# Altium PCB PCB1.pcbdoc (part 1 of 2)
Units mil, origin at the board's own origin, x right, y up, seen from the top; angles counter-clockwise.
Board outline 2362.2 x 2361.9 mil, 2 copper layers (Top Layer, Bottom Layer), stack 62.2 mil thick; 39 components, 38 nets, 262 pads, 86 vias.
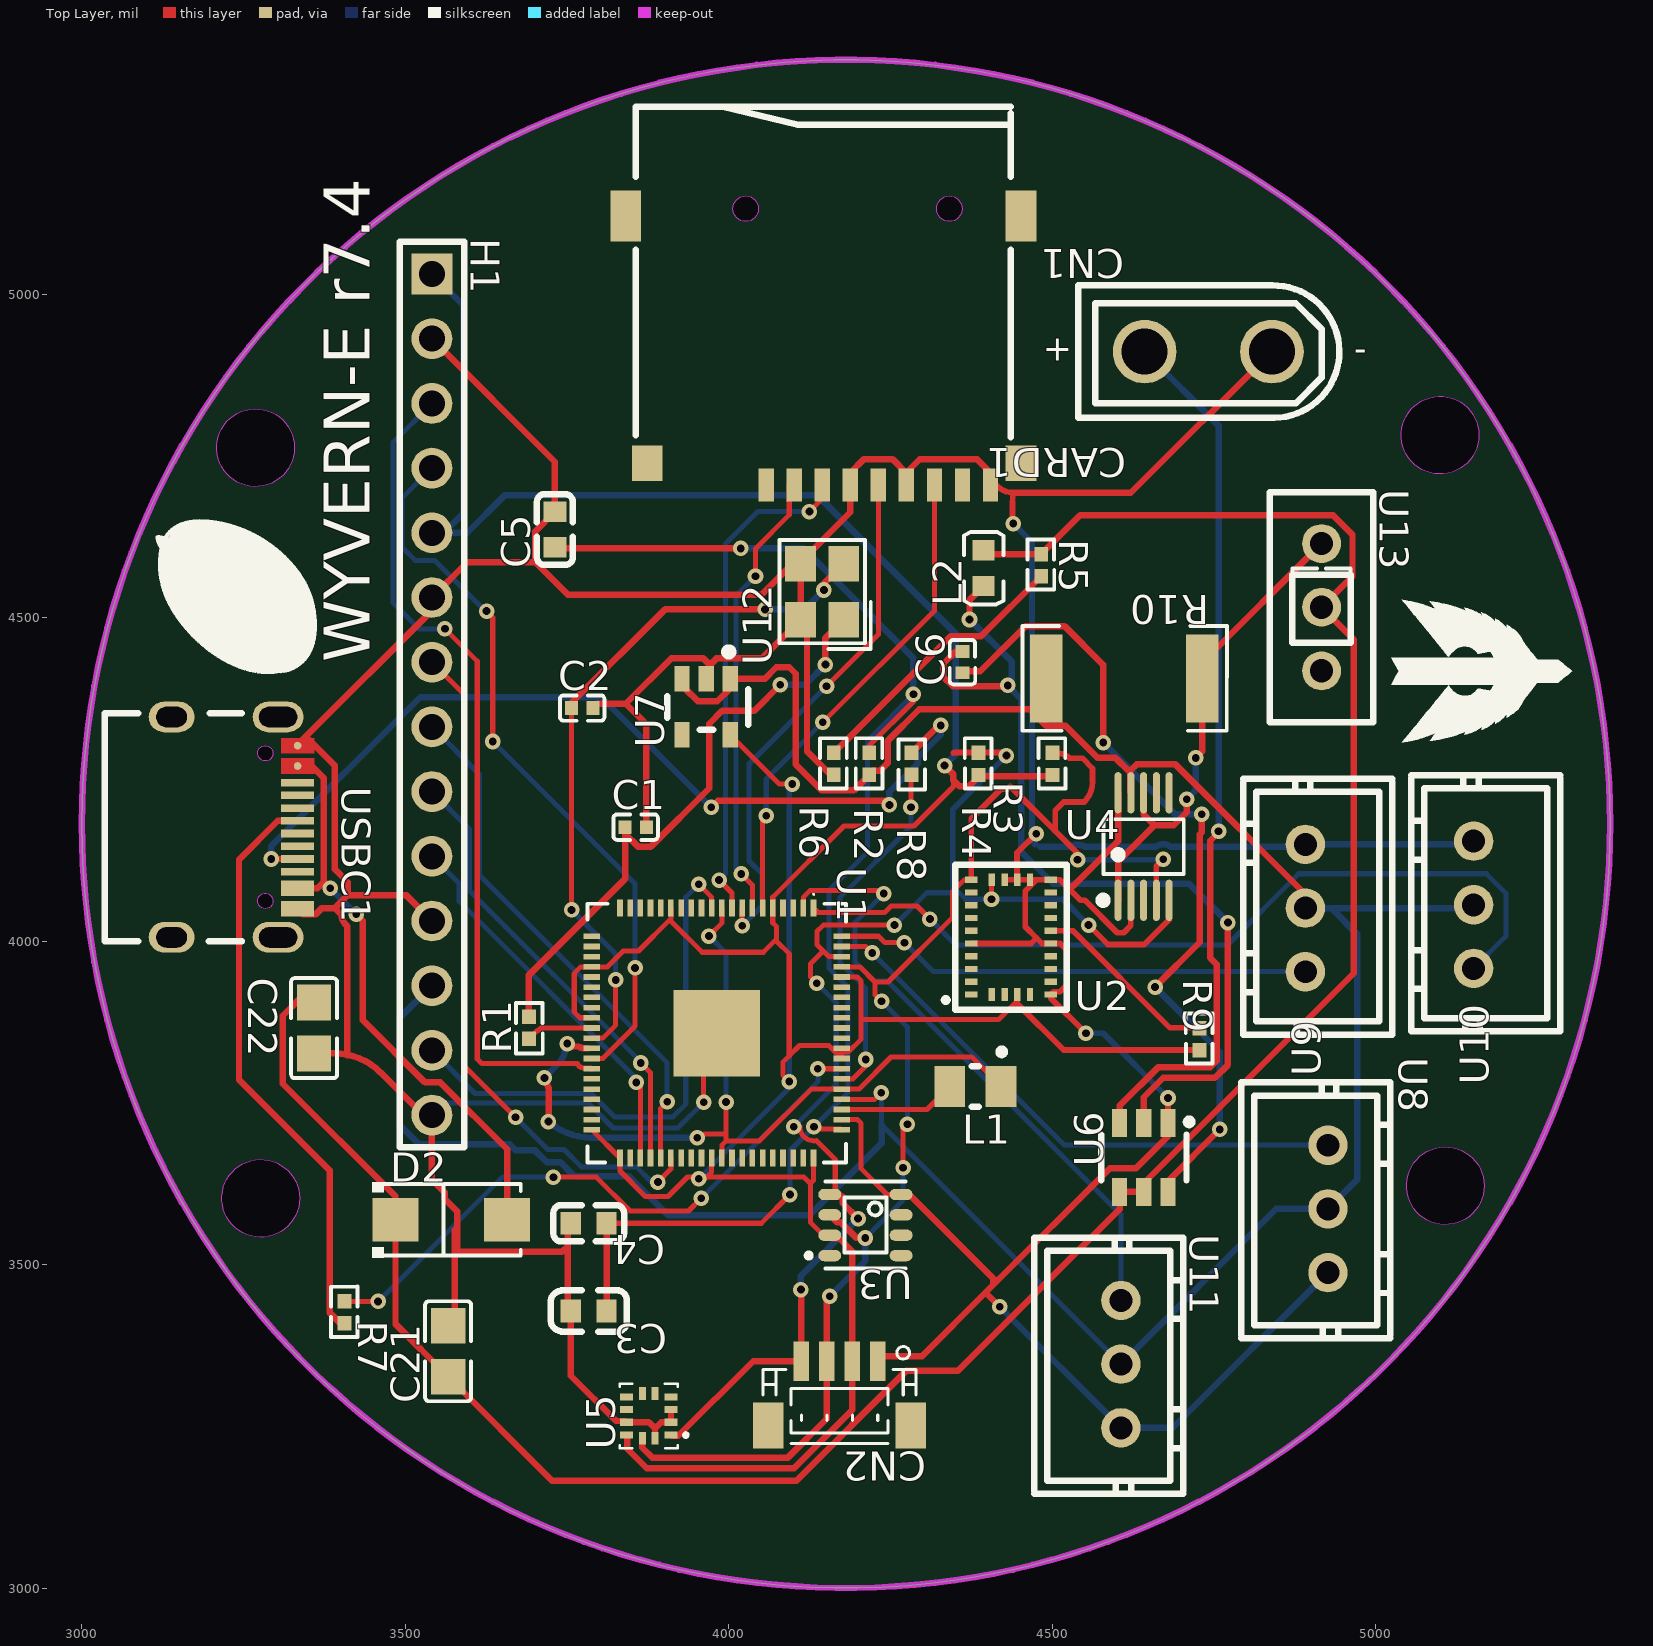
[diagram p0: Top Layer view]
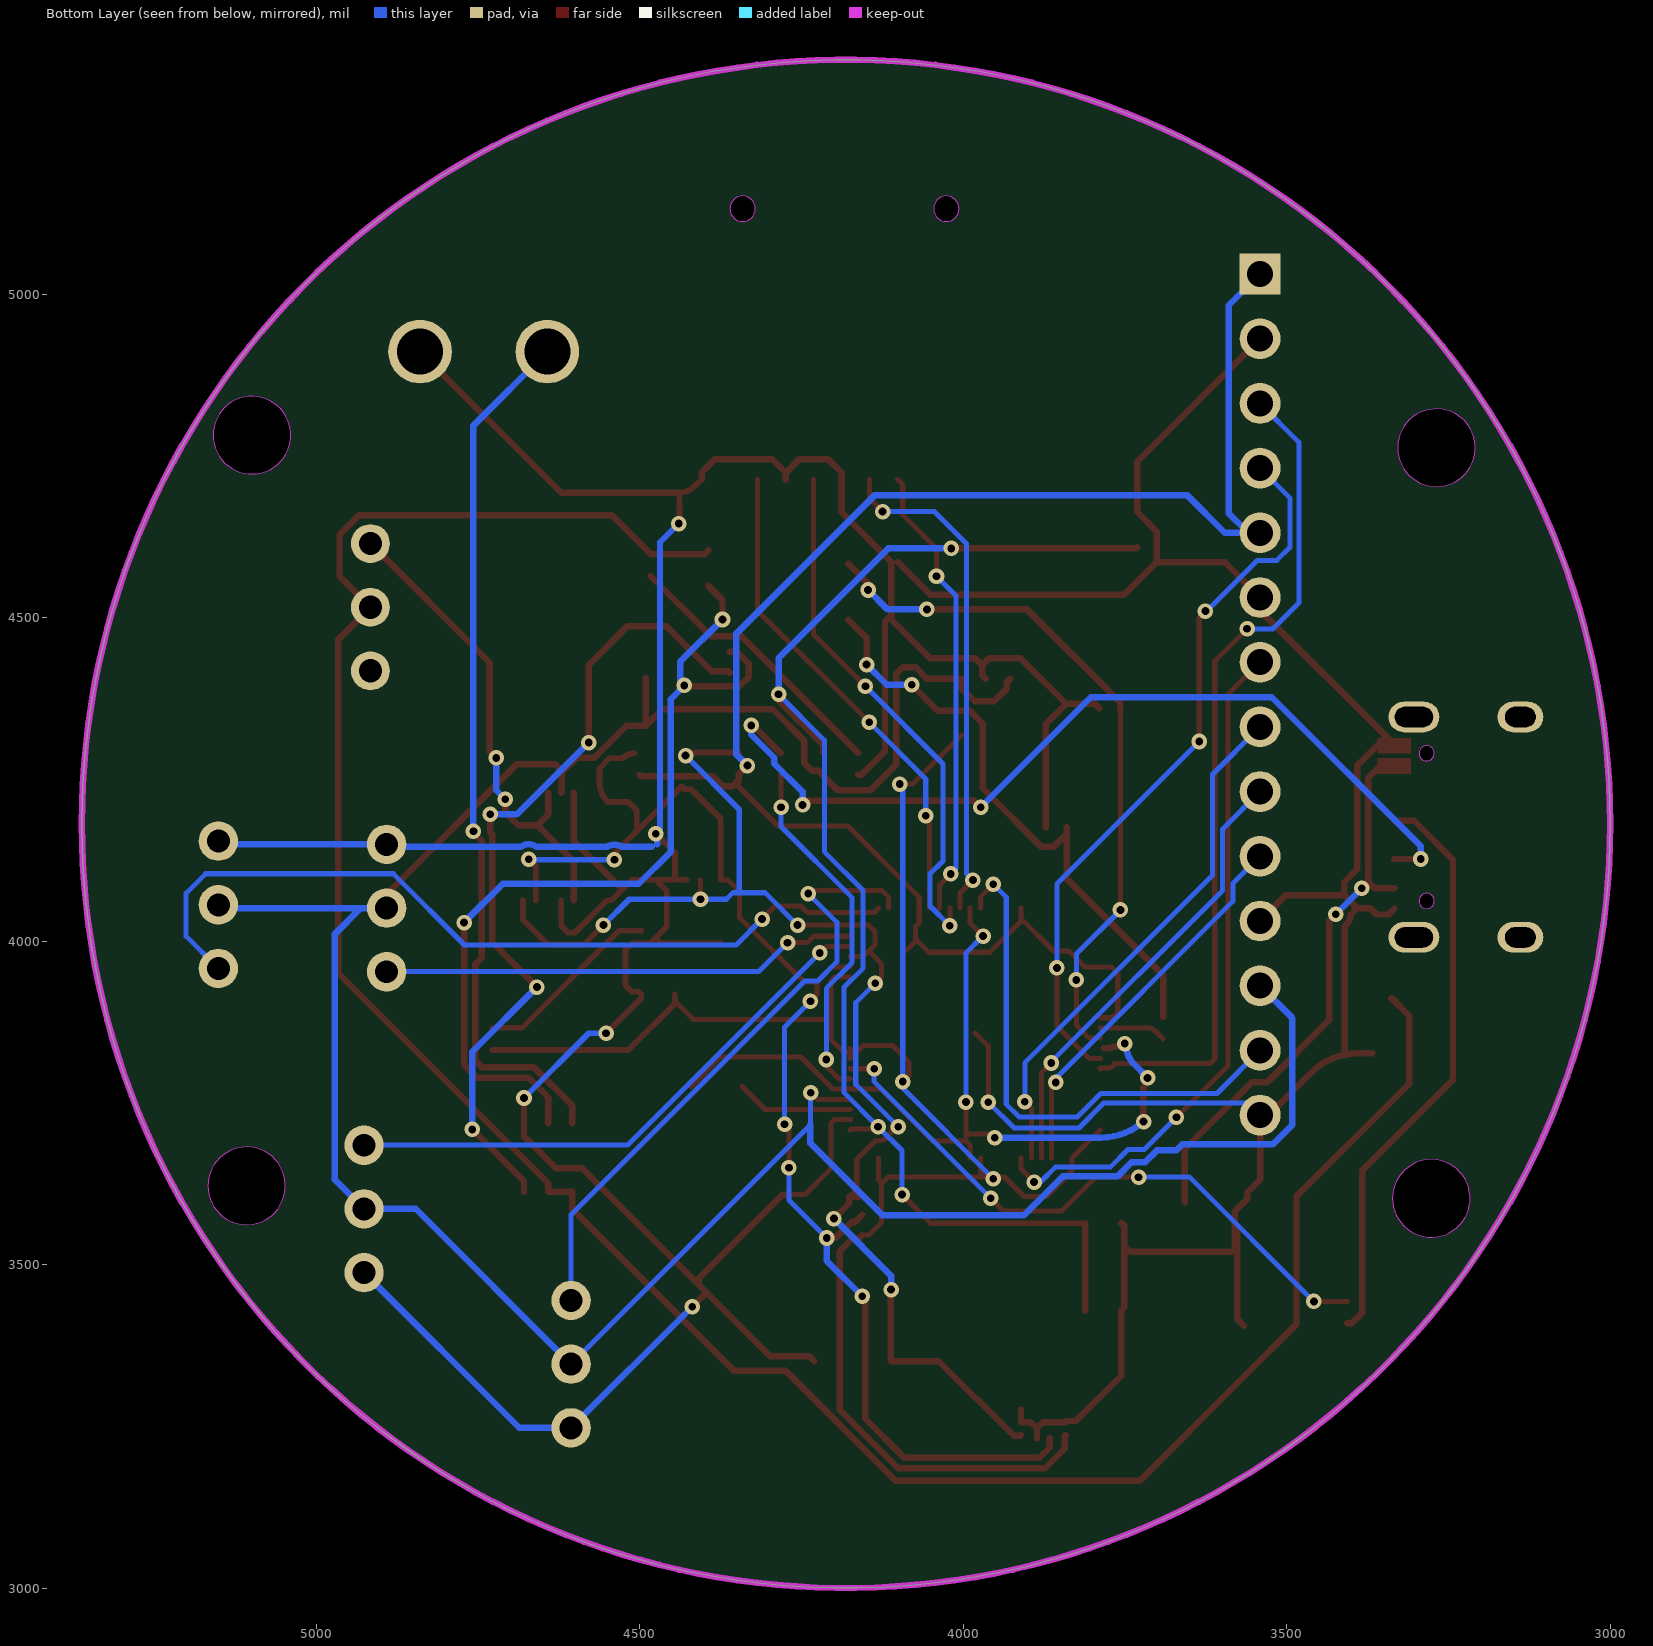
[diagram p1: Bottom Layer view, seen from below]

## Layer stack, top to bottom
Top Solder Mask Layer: solder mask 0.4, Dk 3.3
Top Layer: signal copper 1.4
Dielectric1: surface 59.4, FR4, Dk 4.5
Bottom Layer: signal copper 1.4
Bottom Solder Mask Layer: solder mask 0.4, Dk 3.3

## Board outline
5362.2,4181.1 ccw(c4181.1,4181.1) 3000,4181.1 ccw(c4181.1,4181.1)
cut-out: 3328.4,4762.6 3328,4755.8 3326.8,4749 3324.9,4742.4 3322.2,4736.1 3318.8,4730.2 3314.8,4724.6 3310.2,4719.6 3305,4715.1 3299.3,4711.2 3293.2,4708 3286.9,4705.5 3280.2,4703.8 3273.4,4702.8 3266.6,4702.6 3259.8,4703.2 3253,4704.6 3246.5,4706.7 3240.3,4709.5 3234.4,4713.1 3229,4717.2 3224.1,4722 3219.7,4727.3 3216,4733.1 3213,4739.3 3210.7,4745.7 3209.1,4752.4 3208.4,4759.2 3208.4,4766.1 3209.1,4772.9 3210.7,4779.5 3213,4786 3216,4792.2 3219.7,4797.9 3224.1,4803.2 3229,4808 3234.4,4812.2 3240.3,4815.7 3246.5,4818.6 3253,4820.7 3259.8,4822.1 3266.6,4822.6 3273.4,4822.4 3280.2,4821.5 3286.9,4819.7 3293.2,4817.2 3299.3,4814 3305,4810.2 3310.2,4805.7 3314.8,4800.6 3318.8,4795.1 3322.2,4789.1 3324.9,4782.8 3326.8,4776.2 3328,4769.5
cut-out: 5159.3,4782 5158.9,4775.1 5157.7,4768.4 5155.8,4761.8 5153.1,4755.5 5149.8,4749.5 5145.7,4744 5141.1,4738.9 5135.9,4734.4 5130.3,4730.6 5124.2,4727.4 5117.8,4724.9 5111.2,4723.1 5104.4,4722.2 5097.5,4722 5090.7,4722.5 5084,4723.9 5077.5,4726 5071.2,4728.9 5065.4,4732.4 5059.9,4736.6 5055,4741.4 5050.7,4746.7 5047,4752.4 5043.9,4758.6 5041.6,4765.1 5040.1,4771.7 5039.3,4778.5 5039.3,4785.4 5040.1,4792.2 5041.6,4798.9 5043.9,4805.3 5047,4811.5 5050.7,4817.3 5055,4822.6 5059.9,4827.4 5065.4,4831.5 5071.2,4835.1 5077.5,4837.9 5084,4840 5090.7,4841.4 5097.5,4842 5104.4,4841.8 5111.2,4840.8 5117.8,4839.1 5124.2,4836.6 5130.3,4833.4 5135.9,4829.5 5141.1,4825 5145.7,4820 5149.8,4814.4 5153.1,4808.5 5155.8,4802.2 5157.7,4795.6 5158.9,4788.8
cut-out: 3336.6,3602.4 3336.2,3595.6 3335,3588.8 3333.1,3582.3 3330.4,3575.9 3327,3570 3323,3564.4 3318.4,3559.4 3313.2,3554.9 3307.5,3551 3301.5,3547.8 3295.1,3545.3 3288.5,3543.6 3281.7,3542.6 3274.8,3542.4 3268,3543 3261.3,3544.4 3254.8,3546.5 3248.5,3549.3 3242.6,3552.9 3237.2,3557.1 3232.3,3561.8 3228,3567.1 3224.3,3572.9 3221.2,3579.1 3218.9,3585.5 3217.4,3592.2 3216.6,3599 3216.6,3605.9 3217.4,3612.7 3218.9,3619.4 3221.2,3625.8 3224.3,3632 3228,3637.7 3232.3,3643 3237.2,3647.8 3242.6,3652 3248.5,3655.5 3254.8,3658.4 3261.3,3660.5 3268,3661.9 3274.8,3662.5 3281.7,3662.3 3288.5,3661.3 3295.1,3659.5 3301.5,3657.1 3307.5,3653.9 3313.2,3650 3318.4,3645.5 3323,3640.4 3327,3634.9 3330.4,3628.9 3333.1,3622.6 3335,3616 3336.2,3609.3
cut-out: 5167.5,3621.8 5167.1,3614.9 5166,3608.2 5164,3601.6 5161.4,3595.3 5158,3589.3 5154,3583.8 5149.3,3578.7 5144.1,3574.2 5138.5,3570.4 5132.4,3567.2 5126,3564.7 5119.4,3562.9 5112.6,3562 5105.8,3561.8 5098.9,3562.4 5092.2,3563.7 5085.7,3565.8 5079.5,3568.7 5073.6,3572.2 5068.2,3576.4 5063.2,3581.2 5058.9,3586.5 5055.2,3592.3 5052.2,3598.4 5049.9,3604.9 5048.3,3611.5 5047.5,3618.4 5047.5,3625.2 5048.3,3632 5049.9,3638.7 5052.2,3645.2 5055.2,3651.3 5058.9,3657.1 5063.2,3662.4 5068.2,3667.2 5073.6,3671.3 5079.5,3674.9 5085.7,3677.7 5092.2,3679.9 5098.9,3681.2 5105.8,3681.8 5112.6,3681.6 5119.4,3680.6 5126,3678.9 5132.4,3676.4 5138.5,3673.2 5144.1,3669.3 5149.3,3664.8 5154,3659.8 5158,3654.2 5161.4,3648.3 5164,3642 5166,3635.4 5167.1,3628.6

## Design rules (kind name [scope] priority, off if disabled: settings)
BoardOutlineClearance safeClearance [All] p0: genericclearance=10 ignorepadtopadclearanceinfootprint=FALSE except(0: Arc-SplitContinuation Track-SplitContinuation SMDPad-SplitContinuation THPad-SplitContinuation Via-SplitContinuation Fill-SplitContinuation Poly-SplitContinuation Region-SplitContinuation Text-SplitContinuation)
BoardOutlineClearance otherClearance [All] p0: genericclearance=10 ignorepadtopadclearanceinfootprint=FALSE except(0: Arc-SplitContinuation Track-SplitContinuation SMDPad-SplitContinuation THPad-SplitContinuation Via-SplitContinuation Fill-SplitContinuation Poly-SplitContinuation Region-SplitContinuation Text-SplitContinuation)
Clearance safeClearance [All] p1: gap=7 ignorepadtopadclearanceinfootprint=FALSE
Clearance otherClearance [All] p1: gap=7 ignorepadtopadclearanceinfootprint=FALSE
DiffPairsRouting differentialPair [All] p1: maxuncoupledlength=10 minlimit=6 maxlimit=Infinity mostfreqgap=6 toplayer_minwidth=5 toplayer_prefwidth=10 toplayer_maxwidth=100 bottomlayer_minwidth=5 bottomlayer_prefwidth=10 bottomlayer_maxwidth=100
PasteMaskExpansion pasteMaskExpansion [All] p1: expansion=0
PlaneConnect innerPlane [All] p1: planeconnectstyle=Relief reliefexpansion=20 reliefentries=4 reliefconductorwidth=10 reliefairgap=10
PolygonConnect copperRegion [All] p1: connectstyle=Relief reliefentries=4 reliefconductorwidth=10 polygonreliefangle="90 Angle" airgapwidth=10
RoutingVias viaSize [All] p1: viastyle="Through Hole" holewidth=12.0078 minholewidth=11.811 maxholewidth=236.2204 width=12.0078 minwidth=11.811 maxwidth=236.2204
SolderMaskExpansion solderMaskExpansion [IsVia] p1: useseparateexpansions=TRUE expansion=-1000 expansionbottom=-1000
SolderMaskExpansion solderMaskExpansion [All] p2: useseparateexpansions=TRUE expansion=0.9843 expansionbottom=2.0079
Width trackWidth [All] p1: maxlimit=100 minlimit=5 preferedwidth=10

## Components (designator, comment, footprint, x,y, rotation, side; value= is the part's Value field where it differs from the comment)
C1 "15pF" C0402#1 3856.1,4176.1 r0 top
C2 "15pF" C0402#2 3773.4,4360.2 r0 top
C3 "4.7uF" C0603 3783.4,3428.3 r180 top
C4 "4.7uF" C0603 3783.4,3563.9 r180 top
C5 "4.7uF" C0603 3731.1,4636.1 r90 top
C6 "100nF" C0402#1 4361.1,4431.1 r90 top
C21 "22uF" C0805 3566.1,3366.1 r90 top
C22 "22uF" C0805 3358.8,3865.5 r270 top
CARD1 "TF-01A" TF-SMD_TF-01A 4146.1,4912.9 r180 top
CN1 "XT30UPB-M" CONN-TH_XT30UPB-M 4741.1,4911.1 r180 top
CN2 "BM04B-SRSS-TB(LF)(SN)" CONN-SMD_BM04B-SRSS-TB 4171.1,3301.1 r180 top
D2 "SS14" SMA_L4.4-W2.6-LS5.0-RD 3571.1,3569.1 r0 top
H1 "2011-1X14G00SB" HDR-TH_14P-P2.54-V-M_4 3541.1,4381.1 r270 top
L1 "3.3uH" IND-SMD_L2.0-W1.6_AOTA-B201610S3R3-101-T 4381.3,3775.4 r0 top
L2 "2.2uH" L0603 4393.8,4576.4 r90 top
R1 "1kΩ" R0402#1 3691.1,3866.1 r90 top
R2 "33Ω" R0402#2 4217.2,4273.9 r270 top
R3 "10kΩ" R0402#3 4500.1,4273.7 r270 top
R4 "10kΩ" R0402#3 4385.9,4273.7 r270 top
R5 "56kΩ" R0402#2 4482.9,4581.2 r270 top
R6 "10.2kΩ" R0402#2 4162.3,4273.9 r270 top
R7 "27Ω" R0402#1 3406.1,3426.1 r270 top
R8 "27Ω" R0402#3 4282.2,4273.9 r90 top
R9 "10kΩ" R0402#2 4727.5,3848.6 r270 top
R10 "10mΩ" R2512 4611.1,4406.1 r180 top
U1 "RP2350B" QFN-80_L10.0-W10.0-P0.40-TL-EP3.4 3981.3,3857.8 r270 top
U2 "BNO055" LGA-28_L5.2-W3.8-P0.50-BL 4436.1,4006.1 r0 top
U3 "BME680" LGA-8_L3.0-W3.0-P0.80-TR 4211.1,3561.1 r180 top
U4 "INA226AIDGSR" MSOP-10_L3.0-W3.0-P0.50-LS5.0-BL 4641.1,4146.1 r0 top
U5 "LIS3MDLTR" LGA-12_L2.0-W2.0-P0.50-BL 3876.1,3266.1 r90 top
U6 "TPS563201DDCR" SOT-23-6_L2.9-W1.6-P0.95-LS2.8-BR 4641.4,3665.4 r90 top
U7 "AP2112K-3.3TRG1" SOT-23-5_L2.9-W1.6-P0.95-LS2.8-BR 3964.9,4361.9 r90 top
U8 "B3B-XH-A(LF)(SN)" CONN-TH_3P-P2.50_A2501WV2-3P 4926.1,3586.1 r270 top
U9 "B3B-XH-A(LF)(SN)" CONN-TH_3P-P2.50_A2501WV2-3P 4891.1,4051.1 r90 top
U10 "B3B-XH-A(LF)(SN)" CONN-TH_3P-P2.50_A2501WV2-3P 5151.1,4056.1 r90 top
U11 "B3B-XH-A(LF)(SN)" CONN-TH_3P-P2.50_A2501WV2-3P 4606.1,3346.1 r270 top
U12 "12MHz" CRYSTAL-SMD_4P-L3.2-W2.5-BL 4144.2,4540.2 r90 top
U13 "SS-12D00-G3" SW-TH_3P-L8.8-W3.9-P2.50_SS12D00G3 4916.1,4516.1 r270 top
USBC1 "TYPE-C-31-M-12" USB-C_SMD-TYPE-C-31-M-12_1 3236.1,4176.1 r270 top

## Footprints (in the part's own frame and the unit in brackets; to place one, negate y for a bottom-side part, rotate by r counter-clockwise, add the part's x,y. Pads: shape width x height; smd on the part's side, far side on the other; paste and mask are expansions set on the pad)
C0402#1 [mil]
  rect 19.7x21.3 smd: 1(-16.5,0) 2(16.5,0)
  silkscreen extent -34,-20 34,20
C0402#2 [mil]
  rect 19.7x21.3 smd: 1(-16.5,0) 2(16.6,0)
  silkscreen extent -34,-20 34,20
C0603 [mil]
  rect 31.5x35.4 smd: 1(-27.6,0) 2(27.6,0)
  silkscreen extent -59,-32 59,32
C0805 [mil]
  rect 55.5x53.1 smd paste-3937 mask+2: 1(-39.4,0) 2(39.4,0)
  silkscreen extent -77,-36 77,36
CONN-SMD_BM04B-SRSS-TB [mil]
  rect 47.2x70.9 smd: 0(-110.2,49.7) 0(110.2,49.7)
  rect 23.6x61 smd: 1(-59.1,-49.7) 2(-19.7,-49.7) 3(19.7,-49.7) 4(59.1,-49.7)
  silkscreen extent -118,-72 118,77
CONN-TH_3P-P2.50_A2501WV2-3P [mil]
  round 61 hole 35.4: 1(-98.4,0) 2(0,0) 3(98.4,0)
  silkscreen extent -196,-134 200,96
CONN-TH_XT30UPB-M [mil]
  round 98.4 hole 70.9: 1(-98.4,0) 2(98.4,0)
  silkscreen extent -202,-102 201,102
CRYSTAL-SMD_4P-L3.2-W2.5-BL [mil]
  rect 55.1x47.2 smd: 1(-43.3,-33.5) 2(43.3,-33.5) 3(43.3,33.4) 4(-43.3,33.4)
  silkscreen extent -89,-75 80,66
HDR-TH_14P-P2.54-V-M_4 [mil]
  rect 63x63 hole 40.2: 1(-650,0)
  round 63 hole 40.2: 2(-550,0) 3(-450,0) 4(-350,0) 5(-250,0) 6(-150,0) 7(-50,0) 8(50,0) 9(150,0) 10(250,0) 11(350,0) 12(450,0) 13(550,0) 14(650,0)
  silkscreen extent -700,-50 700,50
IND-SMD_L2.0-W1.6_AOTA-B201610S3R3-101-T [mil]
  rect 47.2x63 smd paste+0 mask+0: 1(-40,0) 2(39.4,0)
  silkscreen extent -6,-32 46,58
L0603 [mil]
  rect 31.5x34 smd paste-3937 mask+2: 1(-27.5,0) 2(27.6,0)
  silkscreen extent -56,-31 56,31
LGA-8_L3.0-W3.0-P0.80-TR [mil]
  oval 35.4x17.6 smd paste+0 mask+0: 1(55.1,47.2) 2(55.1,15.7) 3(55.1,-15.8) 4(55.1,-47.2) 5(-55.1,-47.2) 6(-55.1,-15.8) 7(-55.1,15.7) 8(-55.1,47.2)
  silkscreen extent -62,-67 92,67
LGA-12_L2.0-W2.0-P0.50-BL [mil]
  rect 11x19.7 smd: 1(-29.5,-34.5) 2(-9.8,-34.5) 3(9.8,-34.5) 4(29.5,-34.5) 7(29.5,34.4) 8(9.8,34.4) 9(-9.8,34.4) 10(-29.5,34.4)
  rect 19.7x11 smd: 5(34.5,-9.8) 6(34.5,9.8) 11(-34.4,9.8) 12(-34.4,-9.8)
  silkscreen extent -50,-60 50,45
LGA-28_L5.2-W3.8-P0.50-BL [mil]
  rect 19.7x9.8 smd: 1(-61.5,-88.6) 6(61.5,-88.6) 7(61.5,-68.9) 8(61.5,-49.2) 9(61.5,-29.5) 10(61.5,-9.8) 11(61.5,9.8) 12(61.5,29.5) 13(61.5,49.2) 14(61.5,68.9) 15(61.5,88.6) 20(-61.5,88.6) 21(-61.5,68.9) 22(-61.5,49.2) 23(-61.5,29.5) 24(-61.5,9.8) 25(-61.5,-9.8) 26(-61.5,-29.5) 27(-61.5,-49.2) 28(-61.5,-68.9)
  rect 9.8x19.7 smd: 2(-29.5,-88.6) 3(-9.8,-88.6) 4(9.8,-88.6) 5(29.5,-88.6) 16(29.5,88.6) 17(9.8,88.6) 18(-9.8,88.6) 19(-29.5,88.6)
  silkscreen extent -105,-112 86,112
MSOP-10_L3.0-W3.0-P0.50-LS5.0-BL [mil]
  oval 11x63.8 smd paste+0 mask+0: 1(-39.4,-83.1) 2(-19.7,-83.1) 3(0,-83.1) 4(19.7,-83.1) 5(39.4,-83.1) 6(39.4,83.1) 7(19.7,83.1) 8(0,83.1) 9(-19.7,83.1) 10(-39.4,83.1)
  silkscreen extent -69,-89 62,42
QFN-80_L10.0-W10.0-P0.40-TL-EP3.4 [mil]
  rect 26.2x8.7 smd: 1(-193.3,149.6) 2(-193.3,133.9) 3(-193.3,118.1) 4(-193.3,102.4) 5(-193.3,86.6) 6(-193.3,70.9) 7(-193.3,55.1) 8(-193.3,39.4) 9(-193.3,23.6) 10(-193.3,7.9) 11(-193.3,-7.9) 12(-193.3,-23.6) 13(-193.3,-39.4) 14(-193.3,-55.1) 15(-193.3,-70.9) 16(-193.3,-86.6) 17(-193.3,-102.4) 18(-193.3,-118.1) 19(-193.3,-133.9) 20(-193.3,-149.6) 41(193.2,-149.6) 42(193.2,-133.9) 43(193.2,-118.1) 44(193.2,-102.4) 45(193.2,-86.6) 46(193.2,-70.9) 47(193.2,-55.1) 48(193.2,-39.4) 49(193.2,-23.6) 50(193.2,-7.9) 51(193.2,7.9) 52(193.2,23.6) 53(193.2,39.4) 54(193.2,55.1) 55(193.2,70.9) 56(193.2,86.6) 57(193.2,102.4) 58(193.2,118.1) 59(193.2,133.9) 60(193.2,149.6)
  rect 8.7x26.2 smd: 21(-149.7,-193.2) 22(-133.9,-193.2) 23(-118.2,-193.2) 24(-102.4,-193.2) 25(-86.7,-193.2) 26(-70.9,-193.2) 27(-55.2,-193.2) 28(-39.4,-193.2) 29(-23.7,-193.2) 30(-7.9,-193.2) 31(7.8,-193.2) 32(23.6,-193.2) 33(39.3,-193.2) 34(55.1,-193.2) 35(70.8,-193.2) 36(86.6,-193.2) 37(102.3,-193.2) 38(118.1,-193.2) 39(133.8,-193.2) 40(149.6,-193.2) 61(149.6,193.2) 62(133.8,193.2) 63(118.1,193.2) 64(102.3,193.2) 65(86.6,193.2) 66(70.8,193.2) 67(55.1,193.2) 68(39.3,193.2) 69(23.6,193.2) 70(7.8,193.2) 71(-7.9,193.2) 72(-23.7,193.2) 73(-39.4,193.2) 74(-55.2,193.2) 75(-70.9,193.2) 76(-86.7,193.2) 77(-102.4,193.2) 78(-118.2,193.2) 79(-133.9,193.2) 80(-149.7,193.2)
  rect 133.9x133.9 smd: 81(0,0)
  silkscreen extent -215,-200 200,200
R0402#1 [mil]
  rect 22.3x21.3 smd paste-3937 mask+2: 1(-17,0) 2(17,0)
  silkscreen extent -40,-21 38,20
R0402#2 [mil]
  rect 22.3x21.3 smd paste-3937 mask+2: 1(-17,0) 2(17.1,0)
  silkscreen extent -40,-21 38,20
R0402#3 [mil]
  rect 22.3x21.3 smd paste-3937 mask+2: 1(-17.1,0) 2(17,0)
  silkscreen extent -40,-21 38,20
R2512 [mil]
  rect 50.5x136.1 smd paste-3937 mask+2: 1(-120.7,0) 2(120.7,0)
  silkscreen extent -159,-81 157,81
SMA_L4.4-W2.6-LS5.0-RD [mil]
  rect 70.9x66.9 smd: 1(-86.3,0) 2(86.3,0)
  silkscreen extent -122,-58 107,58
SOT-23-5_L2.9-W1.6-P0.95-LS2.8-BR [mil]
  rect 39.4x23.6 smd paste+0 mask+2: 1(43.3,-37.4) 2(43.3,0) 3(43.3,37.4) 4(-43.3,37.4) 5(-43.3,-37.4)
  silkscreen extent -35,-65 91,60
SOT-23-6_L2.9-W1.6-P0.95-LS2.8-BR [mil]
  rect 43.3x23.6 smd paste+0 mask+2: 1(53.2,-37.4) 2(53.2,0) 3(53.2,37.4) 4(-53.1,37.4) 5(-53.1,0) 6(-53.1,-37.4)
  silkscreen extent -35,-75 60,66
SW-TH_3P-L8.8-W3.9-P2.50_SS12D00G3 [mil]
  round 60 hole 36 paste+0 mask+2: 1(-98.4,0) 2(0,0) 3(98.4,0)
  silkscreen extent -178,-80 178,80
TF-SMD_TF-01A [mil]
  rect 23.6x51.2 smd: 1(88.2,207.8) 2(44.9,207.8) 3(1.6,207.8) 4(-41.7,207.8) 5(-85,207.8) 6(-128.3,207.8) 7(-171.7,207.8) 8(-215,207.8) 9(-258.3,207.7)
  rect 47.2x55.1 smd: 10(-305.5,174.3) 13(272.4,174.3)
  rect 47.2x78.7 smd paste+0 mask+0: 11(-305.5,-207.7) 12(305.5,-207.7)
  Board Outline Layer lines w0.1: 139.8,-219.1 139.4,-222.9 138.3,-226.6 136.4,-230 134,-233 131,-235.5 127.6,-237.3 123.9,-238.4 120.1,-238.8 116.2,-238.4 112.5,-237.3 109.1,-235.5 106.2,-233 103.7,-230 101.9,-226.6 100.8,-222.9 100.4,-219.1 100.8,-215.3 101.9,-211.6 103.7,-208.2 106.2,-205.2 109.1,-202.7 112.5,-200.9 116.2,-199.8 120.1,-199.4 123.9,-199.8 127.6,-200.9 131,-202.7 134,-205.2 136.4,-208.2 138.3,-211.6 139.4,-215.3 139.8,-219.1 ; -175.2,-219.1 -175.6,-222.9 -176.7,-226.6 -178.5,-230 -181,-233 -183.9,-235.5 -187.3,-237.3 -191,-238.4 -194.9,-238.8 -198.7,-238.4 -202.4,-237.3 -205.8,-235.5 -208.8,-233 -211.2,-230 -213.1,-226.6 -214.2,-222.9 -214.6,-219.1 -214.2,-215.3 -213.1,-211.6 -211.2,-208.2 -208.8,-205.2 -205.8,-202.7 -202.4,-200.9 -198.7,-199.8 -194.9,-199.4 -191,-199.8 -187.3,-200.9 -183.9,-202.7 -181,-205.2 -178.5,-208.2 -176.7,-211.6 -175.6,-215.3 -175.2,-219.1
  Board Outline Layer region: -175.2,-219.1 -175.6,-222.9 -176.7,-226.6 -178.5,-230 -181,-233 -183.9,-235.5 -187.3,-237.3 -191,-238.4 -194.9,-238.8 -198.7,-238.4 -202.4,-237.3 -205.8,-235.5 -208.8,-233 -211.2,-230 -213.1,-226.6 -214.2,-222.9 -214.6,-219.1 -214.2,-215.3 -213.1,-211.6 -211.2,-208.2 -208.8,-205.2 -205.8,-202.7 -202.4,-200.9 -198.7,-199.8 -194.9,-199.4 -191,-199.8 -187.3,-200.9 -183.9,-202.7 -181,-205.2 -178.5,-208.2 -176.7,-211.6 -175.6,-215.3
  Board Outline Layer region: -175.2,-219.1 -175.6,-222.9 -176.7,-226.6 -178.5,-230 -181,-233 -183.9,-235.5 -187.3,-237.3 -191,-238.4 -194.9,-238.8 -198.7,-238.4 -202.4,-237.3 -205.8,-235.5 -208.8,-233 -211.2,-230 -213.1,-226.6 -214.2,-222.9 -214.6,-219.1 -214.2,-215.3 -213.1,-211.6 -211.2,-208.2 -208.8,-205.2 -205.8,-202.7 -202.4,-200.9 -198.7,-199.8 -194.9,-199.4 -191,-199.8 -187.3,-200.9 -183.9,-202.7 -181,-205.2 -178.5,-208.2 -176.7,-211.6 -175.6,-215.3
  Board Outline Layer region: 139.8,-219.1 139.4,-222.9 138.3,-226.6 136.4,-230 134,-233 131,-235.5 127.6,-237.3 123.9,-238.4 120.1,-238.8 116.2,-238.4 112.5,-237.3 109.1,-235.5 106.2,-233 103.7,-230 101.9,-226.6 100.8,-222.9 100.4,-219.1 100.8,-215.3 101.9,-211.6 103.7,-208.2 106.2,-205.2 109.1,-202.7 112.5,-200.9 116.2,-199.8 120.1,-199.4 123.9,-199.8 127.6,-200.9 131,-202.7 134,-205.2 136.4,-208.2 138.3,-211.6 139.4,-215.3
  Board Outline Layer region: 139.8,-219.1 139.4,-222.9 138.3,-226.6 136.4,-230 134,-233 131,-235.5 127.6,-237.3 123.9,-238.4 120.1,-238.8 116.2,-238.4 112.5,-237.3 109.1,-235.5 106.2,-233 103.7,-230 101.9,-226.6 100.8,-222.9 100.4,-219.1 100.8,-215.3 101.9,-211.6 103.7,-208.2 106.2,-205.2 109.1,-202.7 112.5,-200.9 116.2,-199.8 120.1,-199.4 123.9,-199.8 127.6,-200.9 131,-202.7 134,-205.2 136.4,-208.2 138.3,-211.6 139.4,-215.3
  Multi-Layer board cut-out: -175.2,-219.1 -175.6,-222.9 -176.7,-226.6 -178.5,-230 -181,-233 -183.9,-235.5 -187.3,-237.3 -191,-238.4 -194.9,-238.8 -198.7,-238.4 -202.4,-237.3 -205.8,-235.5 -208.8,-233 -211.2,-230 -213.1,-226.6 -214.2,-222.9 -214.6,-219.1 -214.2,-215.3 -213.1,-211.6 -211.2,-208.2 -208.8,-205.2 -205.8,-202.7 -202.4,-200.9 -198.7,-199.8 -194.9,-199.4 -191,-199.8 -187.3,-200.9 -183.9,-202.7 -181,-205.2 -178.5,-208.2 -176.7,-211.6 -175.6,-215.3
  Multi-Layer board cut-out: 139.8,-219.1 139.4,-222.9 138.3,-226.6 136.4,-230 134,-233 131,-235.5 127.6,-237.3 123.9,-238.4 120.1,-238.8 116.2,-238.4 112.5,-237.3 109.1,-235.5 106.2,-233 103.7,-230 101.9,-226.6 100.8,-222.9 100.4,-219.1 100.8,-215.3 101.9,-211.6 103.7,-208.2 106.2,-205.2 109.1,-202.7 112.5,-200.9 116.2,-199.8 120.1,-199.4 123.9,-199.8 127.6,-200.9 131,-202.7 134,-205.2 136.4,-208.2 138.3,-211.6 139.4,-215.3
  silkscreen extent -290,-377 290,134
USB-C_SMD-TYPE-C-31-M-12_1 [mil]
  oval 47.2x78.7 hole 31.5 slot 59.1 at 90 deg paste+0 mask+2: 1(170.3,67.2) 4(-170.3,67.2)
  oval 47.2x70.9 hole 31.5 slot 47.2 at 90 deg paste+0 mask+2: 2(170.3,-97.4) 3(-170.3,-97.4)
  round 11.8 smd: A1B12(-126,97.4) A4B9(-94.5,97.4)
  rect 11.8x51.2 smd paste-3937 mask+0: A5(-49.2,97.4) A6(-9.8,97.4) A7(9.8,97.4) A8(49.2,97.4) B5(68.9,97.4) B6(29.5,97.4) B7(-29.5,97.4) B8(-68.9,97.4)
  rect 23.6x51.2 smd paste-3937 mask+0: B1A12(126,97.4) B4A9(94.5,97.4)
  Top Layer region: -114.2,71.8 -126,71.8 -126,71.8 -137.8,71.8 -137.8,123 -126,123 -126,123 -114.2,123
  Top Layer region: -82.7,71.8 -94.5,71.8 -94.5,71.8 -106.3,71.8 -106.3,123 -94.5,123 -94.5,123 -82.7,123
  Board Outline Layer lines w0.1: 114.9,35.7 117.8,36.2 120.5,37.5 122.8,39.4 124.5,41.8 125.6,44.5 126,47.5 125.6,50.4 124.5,53.2 122.8,55.6 120.5,57.4 117.8,58.7 114.9,59.3 112,59.1 109.1,58.2 106.6,56.6 104.6,54.4 103.2,51.8 102.4,48.9 102.4,46 103.2,43.1 104.6,40.5 106.6,38.4 109.1,36.8 112,35.9 114.9,35.7 ; -113.4,35.7 -110.5,36.2 -107.8,37.5 -105.6,39.4 -103.8,41.8 -102.7,44.5 -102.4,47.5 -102.7,50.4 -103.8,53.2 -105.6,55.6 -107.8,57.4 -110.5,58.7 -113.4,59.3 -116.4,59.1 -119.2,58.2 -121.7,56.6 -123.7,54.4 -125.2,51.8 -125.9,48.9 -125.9,46 -125.2,43.1 -123.7,40.5 -121.7,38.4 -119.2,36.8 -116.4,35.9 -113.4,35.7
  Board Outline Layer region: -102.4,47.5 -102.7,44.5 -103.8,41.8 -105.6,39.4 -107.8,37.5 -110.5,36.2 -113.4,35.7 -116.4,35.9 -119.2,36.8 -121.7,38.4 -123.7,40.5 -125.2,43.1 -125.9,46 -125.9,48.9 -125.2,51.8 -123.7,54.4 -121.7,56.6 -119.2,58.2 -116.4,59.1 -113.4,59.3 -110.5,58.7 -107.8,57.4 -105.6,55.6 -103.8,53.2 -102.7,50.4
  Board Outline Layer region: -102.4,47.5 -102.7,44.5 -103.8,41.8 -105.6,39.4 -107.8,37.5 -110.5,36.2 -113.4,35.7 -116.4,35.9 -119.2,36.8 -121.7,38.4 -123.7,40.5 -125.2,43.1 -125.9,46 -125.9,48.9 -125.2,51.8 -123.7,54.4 -121.7,56.6 -119.2,58.2 -116.4,59.1 -113.4,59.3 -110.5,58.7 -107.8,57.4 -105.6,55.6 -103.8,53.2 -102.7,50.4
  Board Outline Layer region: 126,47.5 125.6,44.5 124.5,41.8 122.8,39.4 120.5,37.5 117.8,36.2 114.9,35.7 112,35.9 109.1,36.8 106.6,38.4 104.6,40.5 103.2,43.1 102.4,46 102.4,48.9 103.2,51.8 104.6,54.4 106.6,56.6 109.1,58.2 112,59.1 114.9,59.3 117.8,58.7 120.5,57.4 122.8,55.6 124.5,53.2 125.6,50.4
  Board Outline Layer region: 126,47.5 125.6,44.5 124.5,41.8 122.8,39.4 120.5,37.5 117.8,36.2 114.9,35.7 112,35.9 109.1,36.8 106.6,38.4 104.6,40.5 103.2,43.1 102.4,46 102.4,48.9 103.2,51.8 104.6,54.4 106.6,56.6 109.1,58.2 112,59.1 114.9,59.3 117.8,58.7 120.5,57.4 122.8,55.6 124.5,53.2 125.6,50.4
  Multi-Layer board cut-out: -102.4,47.5 -102.7,44.5 -103.8,41.8 -105.6,39.4 -107.8,37.5 -110.5,36.2 -113.4,35.7 -116.4,35.9 -119.2,36.8 -121.7,38.4 -123.7,40.5 -125.2,43.1 -125.9,46 -125.9,48.9 -125.2,51.8 -123.7,54.4 -121.7,56.6 -119.2,58.2 -116.4,59.1 -113.4,59.3 -110.5,58.7 -107.8,57.4 -105.6,55.6 -103.8,53.2 -102.7,50.4
  Multi-Layer board cut-out: 126,47.5 125.6,44.5 124.5,41.8 122.8,39.4 120.5,37.5 117.8,36.2 114.9,35.7 112,35.9 109.1,36.8 106.6,38.4 104.6,40.5 103.2,43.1 102.4,46 102.4,48.9 103.2,51.8 104.6,54.4 106.6,56.6 109.1,58.2 112,59.1 114.9,59.3 117.8,58.7 120.5,57.4 122.8,55.6 124.5,53.2 125.6,50.4
  silkscreen extent -176,-201 176,11

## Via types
v1: diameter 24, hole 12, Top Layer to Bottom Layer, 86 vias

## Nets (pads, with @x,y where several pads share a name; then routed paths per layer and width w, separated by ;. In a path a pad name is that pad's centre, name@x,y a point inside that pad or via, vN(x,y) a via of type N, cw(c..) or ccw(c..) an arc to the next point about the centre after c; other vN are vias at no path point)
$1N357: CN2.3 R3.1 U1.77 U2.20 U3.3 U4.4 U5.11 | length 2180.5
  Top Layer w7.8: U1.77@4174.5,3960.2 4202.6,3960.2 4226,3936.9 ; v1(4236,3906.9) 4226,3916.9 4226,3936.9 ; v1(4269.3,3649.8) 4269.3,3710.2 v1(4276,3716.9) ; U2.20@4374.6,4094.7 4363.8,4094.7 4346,4076.9 4346,4036.9 4246,3936.9 4226,3936.9
  Top Layer w8.9: U2.20@4374.6,4094.7 4374.6,4189 4420.3,4234.7 4430.3,4234.7 4435.1,4239.5 4504.4,4170.2 ; 4504.2,4170 4504.4,4170.2 ; R3.1@4508,4290.4 cw(c4508,4264.5) 4526.31,4282.81 4546.5,4282.8 4562.3,4266.9 4562.3,4246.7 cw(c4517.4,4246.7) 4549.15,4214.95 ; v1(4539,4125.8) 4539,4135.7 4504.4,4170.2 ; 4549.2,4215 4517.6,4215 4504.4,4201.8 4504.4,4170.2 ; U4.4@4660.8,4063 4660.8,4115.8 v1(4671.5,4126.5)
  Top Layer w9.9: U5.11@3866.3,3231.7 3866.3,3216.8 3881.4,3201.7 4091.4,3201.7 4151.4,3261.7 CN2.3@4151.4,3350.8
  Top Layer w10: CN2.3@4151.4,3350.8 4151.4,3446.3 v1(4156,3450.9) ; U3.3@4156,3576.9 4167.7,3565.2 4173.1,3565.2 4197.2,3541.1 v1(4210.8,3541.1)
  Bottom Layer w7.8: v1(4210.8,3541.1) 4269.3,3599.6 v1(4269.3,3649.8) ; v1(4236,3906.9) 4276,3866.9 v1(4276,3716.9)
  Bottom Layer w8.9: v1(4539,4125.8) 4670.6,4125.8 v1@4671.4,4126.6
  Bottom Layer w10: v1(4156,3450.9) 4210.8,3505.7 v1(4210.8,3541.1)
$1N359: CN2.4 R4.1 U1.78 U2.19 U3.4 U4.5 U5.1 | length 2122.1
  Top Layer w7.8: v1(4100.5,3713.2) 4109.6,3713.2 ccw(c4131.5,3713.2) 4135.34,3691.64 ; 4135.3,3691.7 4164.5,3662.5 4164.5,3616.2 4176,3604.7 ; v1(4136,3934.7) 4126,3944.7 4126,3964.7 4146,3984.7 ; U1.78@4174.5,3976 4154.8,3976 4146,3984.7 ; v1(4256,4024.7) 4146,4024.7 4136,4014.7 4136,3994.7 4146,3984.7 ; v1(4406,4064.7) 4406,4094.1 U2.19@4406.6,4094.7
  Top Layer w8.9: 4347.1,4290.9 4347.9,4291.7 4424.1,4291.7 v1(4429.1,4286.7) ; v1(4556,4024.7) 4586,3994.7 4642.2,3994.7 4680.5,4033 U4.5@4680.5,4063
  Top Layer w9.9: U5.1@3910.6,3236.6 3911.8,3235.3 3922,3235.3 4037.5,3350.8 CN2.4@4112,3350.8
  Top Layer w10: v1(4111.4,3461.4) 4112,3460.7 CN2.4@4112,3350.8 ; U3.4@4156,3608.3 4159.6,3604.7 4176,3604.7 4176,3594.8 v1(4199.7,3571.1)
  Bottom Layer w7.8: v1(4100.5,3713.2) 4166,3778.7 4166,3904.7 v1(4136,3934.7) ; v1(4256,4024.7) 4306,4074.7 4346,4074.7 4356,4074.7 4366,4064.7 v1(4406,4064.7)
  Bottom Layer w8.9: 4346,4074.7 4346,4203.5 v1(4429.1,4286.7) ; v1(4406,4064.7) 4516,4064.7 v1(4556,4024.7)
  Bottom Layer w10: v1(4111.4,3461.4) 4111.4,3482.8 v1(4199.7,3571.1)
$1N360: R9.1 U2.11 | length 292.1
  Top Layer w8.9: U2.11@4497.6,4015.9 4531.9,4015.9 4681.9,3865.9 4727.1,3865.9 R9.1@4727.5,3865.6
$1N367: C21.1 C22.1 D2.1 L2.2 R5.1 U6.4 U6.5 U13.2 | length 3845.8
  Top Layer w10: C22.1@3338.1,3911.9 3310.7,3884.5 3310.7,3779.7 3484.8,3605.6 D2.1@3484.8,3569.1 3484.8,3408 C21.1@3566.1,3326.7 3727.2,3165.6 4104,3165.6 4274,3335.6 4354,3335.6 4604,3585.6 U6.4@4604,3612.3 U6.5@4641.4,3612.3 4641.4,3625.6 4966.1,3950.4 4966.1,4466.1 U13.2@4916.1,4516.1 4964,4564 4964,4628.2 4934,4658.2 4542.9,4658.2 R5.1@4482.9,4598.2 4399.6,4598.2 L2.2@4393.8,4604
$1N368: R5.2 R6.1 | length 433.8
  Top Layer w10: R6.1@4162.3,4290.9 4342.9,4471.5 4390.3,4471.5 R5.2@4482.9,4564.1
$1N370: C6.2 L2.1 U6.2 | length 1397.7
  Top Layer w10: C6.2@4361.1,4447.6 4350.4,4447.6 4331.4,4428.6 4331.4,4408.3 4345.9,4393.7 4429.7,4393.7 v1(4431,4395.1) ; v1(4372,4497.1) 4372,4527.1 L2.1@4393.8,4548.9 ; U6.2@4641.4,3718.6 4641.4,3758.6 4671.4,3788.6 4751.4,3788.6 4771.4,3808.6 v1(4771.4,4028.6)
  Bottom Layer w10: v1(4372,4497.1) 4437.1,4432 4437.1,4401.2 v1(4431,4395.1) 4452.1,4373.9 4452.1,4137.8 4501.4,4088.6 4711.4,4088.6 v1(4771.4,4028.6)
$1N371: C6.1 U6.6 | length 1278.7
  Top Layer w10: C6.1@4361.1,4414.6 4363.4,4416.9 4388.8,4416.9 4458.8,4486.9 4518.8,4486.9 4578.8,4426.9 v1(4578.8,4306.9) ; v1(4658.8,3929) 4728,3998.2 4728,4165 4730.9,4167.9 v1(4730.9,4196) ; U6.6@4678.8,3612.3 4678.8,3629 v1(4758.8,3709)
  Bottom Layer w10: v1(4578.8,4306.9) 4689.7,4196 v1(4730.9,4196) ; v1(4658.8,3929) 4758.8,3829 v1(4758.8,3709)
$1N373: D2.2 USBC1.A4B9 USBC1.B4A9 | length 880.7
  Top Layer w10: USBC1.B4A9@3333.5,4081.6 3364.1,4081.6 3374.1,4091.6 ; USBC1.A4B9@3333.5,4270.6 3334.5,4271.6 3354.1,4271.6 3374.1,4251.6 3374.1,4091.6 ; v1(3384.1,4081.6) 3374.1,4091.6 ; v1(3424.1,4041.6) 3434.1,4031.6 3434.1,3878 3530.5,3781.6 3554.1,3781.6 3657.4,3678.3 D2.2@3657.4,3596.1
  Bottom Layer w10: v1(3384.1,4081.6) v1(3424.1,4041.6)
$1N378: L1.1 U1.63 | length 182.3
  Top Layer w7.8: U1.63@4174.5,3739.7 4306.3,3739.7 L1.1@4342,3775.4
$1N379: L1.2 U1.10 U1.32 U1.51 U1.65 | length 1355
  Top Layer w7.8: v1(3951.1,3696.1) cw(c3964.7,3682.5) 3964.7,3701.8 ; 3964.7,3701.7 3995.8,3701.7 ; v1(3969.2,4007.8) 3989.2,4027.8 U1.10@3989.2,4051.1 ; U1.51@3989.2,3664.6 3989.2,3684.6 3995.8,3691.2 ; v1(3995.8,3751.2) 3995.8,3701.7 ; L1.2@4420.7,3775.4 4375.3,3820.8 4250.7,3820.8 4201.1,3771.2 U1.65@4174.5,3771.2 4127.5,3771.2 4047.5,3691.2 3995.8,3691.2 ; 3995.8,3691.2 3995.8,3701.7
  Top Layer w10: v1@3714.96,3784.56 cw(c3698.2,3767.8) 3721.9,3767.8 ; v1@3721.8,3722.4 3721.8,3767.8 ; v1@3753.9,3837.1 3768,3837.1 ; 3768.03,3837.09 ccw(c3775,3845.6) 3775,3834.6 U1.32@3782.4,3834.6
  Bottom Layer w7.8: v1(3969.2,4007.8) 3995.8,3981.2 v1(3995.8,3751.2)
  Bottom Layer w10: v1@3714.4,3788.3 3736.4,3810.3 ; v1(3721.1,3721.1) 3716.8,3725.4 ccw(c3787.5,3796.1) 3787.5,3696.1 v1(3951.1,3696.1) ; 3736.47,3810.33 ccw(c3709.1,3837.7) v1@3747.8,3837.7
  other v1: 3714.9,3788.6 3750.1,3841.7
$1N380: C3.1 C4.1 C5.1 R2.1 U1.61 | length 2161.7
  Top Layer w7.8: C4.1@3811,3563.9 4050.2,3563.9 v1(4094.5,3608.2) ; v1(4131.5,3713.2) 4131.5,3709.8 4173,3709.8 U1.61@4174.5,3708.2 ; R2.1@4217.2,4290.9 4217.2,4302.3 4285.4,4370.4 v1(4285.4,4381.5)
  Top Layer w10: C5.1@3731.1,4608.5 3732.8,4606.9 v1(4018.5,4606.9) ; C3.1@3811,3428.3 C4.1@3811,3563.9
  Bottom Layer w7.8: v1(4094.5,3608.2) 4094.5,3676.3 v1(4131.5,3713.2) 4184.5,3766.3 4184.5,3928.2 4154.5,3958.2 4154.5,4078.2 4214.5,4138.2 4214.5,4310.6 v1(4285.4,4381.5)
  Bottom Layer w10: v1(4018.5,4606.9) 4115.9,4606.9 4285.4,4437.4 v1(4285.4,4381.5)
$1N384: C2.1 U1.31 U12.2 | length 1087.6
  Top Layer w7.8: v1(3756.9,4048.2) C2.1@3756.9,4358.2 ; U1.31@3788.1,3850 3805.1,3850 3825.1,3870 v1(3825.1,3940)
  Top Layer w10: C2.1@3756.9,4358.2 C2.1@3756.9,4360.2 3756.9,4368.2 3901.4,4512.7 v1(4056,4512.7) ; v1(4146.9,4542.7) 4146.9,4552.7 U12.2@4177.7,4583.5
  Bottom Layer w7.8: v1(3756.9,4048.2) 3825.1,3980 v1(3825.1,3940)
  Bottom Layer w10: v1(4056,4512.7) 4116.9,4512.7 v1(4146.9,4542.7)
$1N387: R7.2 USBC1.A6 | length 903.6
  Top Layer w10: USBC1.A6@3333.5,4185.9 3302.9,4185.9 3242.9,4125.9 3242.9,3785.9 3382.9,3645.9 3382.9,3425.9 3399.8,3409.1 R7.2@3406.1,3409.1
$1N388: R8.2 USBC1.A8 | length 1406.9
  Top Layer w10: v1(3292.9,4126.9) USBC1.A8@3333.5,4126.9 ; v1(3972.9,4206.9) 3982.9,4216.9 4241.8,4216.9 v1(4248.2,4210.5) ; R8.2@4282.2,4290.9 4324.6,4333.3 v1(4327.5,4333.3)
  Bottom Layer w10: v1(3292.9,4126.9) 3292.9,4146.9 3522.9,4376.9 3802.9,4376.9 v1(3972.9,4206.9) ; v1(4248.2,4210.5) 4248.2,4230.7 4291.8,4274.3 4291.8,4283.2 4327.5,4318.9 v1(4327.5,4333.3)
$1N391: R7.1 U1.67 | length 972.5
  Top Layer w7.8: R7.1@3406.1,3443.1 v1(3457.9,3443.1) ; v1(3728.9,3635.1) 3795.2,3635.1 3847.5,3582.7 3937.5,3582.7 v1(3957.5,3602.7) ; v1(4137.5,3802.7) U1.67@4174.5,3802.7
  Bottom Layer w7.8: v1(3457.9,3443.1) 3649.9,3635.1 v1(3728.9,3635.1) ; v1(3957.5,3602.7) 4137.5,3782.7 v1(4137.5,3802.7)
$1N392: U1.79 U8.1 | length 878.8
  Top Layer w7.8: U1.79@4174.5,3991.7 4211.5,3991.7 v1(4221.5,3981.7)
  Bottom Layer w7.8: v1(4221.5,3981.7) 4518.7,3684.5 U8.1@4926.1,3684.5
$1N393: U1.80 U9.1 | length 739.3
  Top Layer w7.8: U1.80@4174.5,4007.5 4231.5,4007.5 4241.5,3997.5 v1(4271.5,3997.5)
  Bottom Layer w7.8: v1(4271.5,3997.5) 4316.3,3952.7 U9.1@4891.1,3952.7
$1N394: U1.1 U10.1 | length 1296.9
  Top Layer w7.8: U1.1@4130.9,4051.1 4137.9,4044.1 4240.9,4044.1 4250.9,4054.1 4290.9,4054.1 v1(4310.9,4034.1)
  Bottom Layer w7.8: v1(4310.9,4034.1) 4350.9,3994.1 4770.9,3994.1 4880.9,4104.1 5170.9,4104.1 5200.9,4074.1 5200.9,4007.5 U10.1@5151.1,3957.7
$1N395: U1.2 U11.1 | length 976.1
  Top Layer w7.8: U1.2@4115.2,4051.1 4115.2,4068 4125.2,4078 4234.7,4078 v1(4239.3,4073.4)
  Bottom Layer w7.8: v1(4239.3,4073.4) 4195.2,4029.3 4195.2,3968 4225.2,3938 4245.2,3938 4606.1,3577.1 U11.1@4606.1,3444.5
